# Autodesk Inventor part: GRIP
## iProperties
Created: 2010-11
Part Number: GRIP
Document SubType Name: Modeling
Designer: ROBERT
Density: 1 g/cm^3
Author: ROBERT
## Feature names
1. Extrusion1
2. Extrusion2
3. Fillet1
4. Extrusion3
5. Fillet2
